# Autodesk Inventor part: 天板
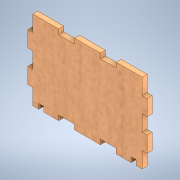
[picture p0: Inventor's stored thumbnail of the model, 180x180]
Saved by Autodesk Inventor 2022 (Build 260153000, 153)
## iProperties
Created: 2024-11
Part Number: 天板
Material: MDF 中密度繊維ボード
Document SubType Name: Modeling
Designer: shimizu
Density: 0.8 g/cm^3
Appearance: サクラ材 - ナチュラル 抑えた光沢
Author: shimizu
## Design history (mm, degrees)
sketch "スケッチ1"
  geometry: L1 (-25.119, 2.566)-(-27.619, 2.566); L2 (-27.619, 2.566)-(-27.619, -5.434); L3 (-27.619, -5.434)-(-25.119, -5.434); L4 (-25.119, -13.434)-(-27.619, -13.434); L5 (-27.619, -13.434)-(-27.619, -21.434); L6 (-27.619, -21.434)-(-25.119, -21.434); L7 (29.881, 2.566)-(32.381, 2.566); L8 (32.381, 2.566)-(32.381, -5.434); L9 (32.381, -5.434)-(29.881, -5.434); L10 (29.881, -13.434)-(32.381, -13.434); L11 (32.381, -13.434)-(32.381, -21.434); L12 (32.381, -21.434)-(29.881, -21.434); L13 (-25.119, 2.566)-(-25.119, 10.566); L14 (-25.119, -29.434)-(-25.119, -21.434); L15 (-25.119, -13.434)-(-25.119, -5.434); L16 (29.881, 10.566)-(29.881, 2.566); L17 (29.881, -5.434)-(29.881, -13.434); L18 (29.881, -21.434)-(29.881, -29.434); L19 (-4.119, -29.434)-(-4.119, -26.934); L20 (-4.119, -26.934)-(-12.119, -26.934); L21 (-12.119, -26.934)-(-12.119, -29.434); L22 (16.881, -29.434)-(16.881, -26.934); L23 (16.881, -26.934)-(8.881, -26.934); L24 (8.881, -26.934)-(8.881, -29.434); L25 (-4.119, 10.566)-(-4.119, 8.066); L26 (-4.119, 8.066)-(-12.119, 8.066); L27 (-12.119, 8.066)-(-12.119, 10.566); L28 (16.881, 10.566)-(16.881, 8.066); L29 (16.881, 8.066)-(8.881, 8.066); L30 (8.881, 8.066)-(8.881, 10.566); L31 (-25.119, 10.566)-(-12.119, 10.566); L32 (-4.119, 10.566)-(8.881, 10.566); L33 (16.881, 10.566)-(29.881, 10.566); L34 (-12.119, -29.434)-(-25.119, -29.434); L35 (29.881, -29.434)-(16.881, -29.434); L36 (8.881, -29.434)-(-4.119, -29.434); L37 (24.381, -29.434)-(26.881, -29.434); L38 (26.881, -29.434)-(26.881, -26.934); L39 (26.881, -26.934)-(24.381, -26.934); L40 (24.381, -26.934)-(24.381, -29.434); L41 (-22.119, -29.434)-(-19.619, -29.434); L42 (-19.619, -29.434)-(-19.619, -26.934); L43 (-19.619, -26.934)-(-22.119, -26.934); L44 (-22.119, -26.934)-(-22.119, -29.434); 3 further points
  constraints: 88 end point, 30 parallel, 15 perpendicular, 9 horizontal, 2 collinear, 2 point on line
  dimensions: "d29" = 55 distance between parallel lines of L17 L15; "d30" = 35 distance between parallel lines of L20 L26; "d31" = 60 distance between parallel lines of L11 L5; "d32" = 13 distance of L21.end L14.start; "d33" = 13 distance of L24.end L19.start; "d34" = 13 distance of L18.end L22.start; "d35" = 13 distance of L13.end L27.end; "d36" = 13 distance of L25.start L30.end; "d37" = 13 distance of L28.start L16.start; "d38" = 8 distance of L28.end L29.end; "d39" = 8 distance of L25.end L26.end; "d40" = 8 distance of L22.end L23.end; "d41" = 8 distance of L19.end L20.end; "d42" = 8 distance of L9.end L10.start; "d43" = 2.5 distance between parallel lines of L40 L38; "d44" = 2.5 distance between parallel lines of L37 L39; "d45" = 3 distance between parallel lines of L38 L18; "d46" = 2.5 distance of L43.end L41.start; "d47" = 2.5 distance of L42.end L43.end; "d48" = 3 distance between parallel lines of L44 L14
extrude "押し出し1" new body sketch "スケッチ1" distance "d2" = 2.5; taper "d3" = 0 deg
node "ソリッド1"
